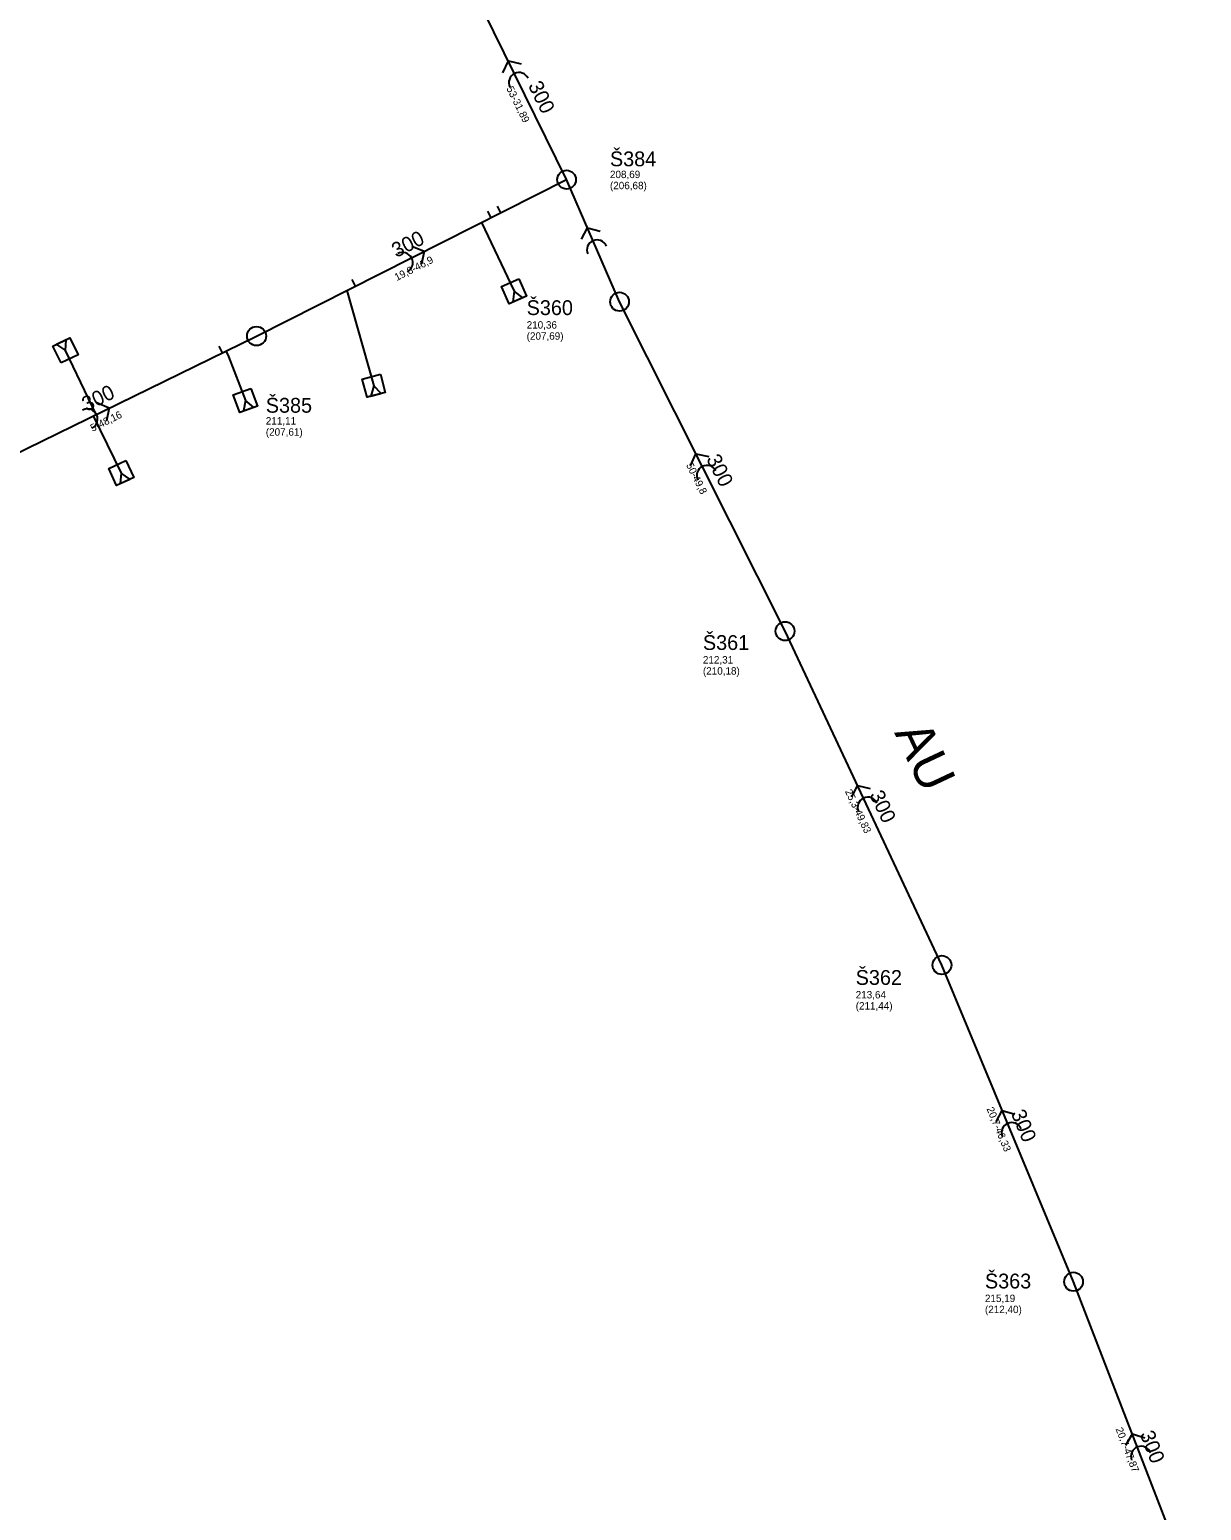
# Model space of a CAD drawing. Extents: x -574467 to -573663, y -1191209 to -1190406.
# Drawn here: x -573886.4 to -573728.1, y -1191008.6 to -1190808.6 of the extents above; entities that cross this region are included whole.
import ezdxf

# ---------------------------------------------------------------- set-up
doc = ezdxf.new("R2010")
doc.units = 0
for name, color, linetype in [('Vrstva 1', 7, 'Continuous'), ('Vrstva 12', 7, 'Continuous'), ('Vrstva 15', 7, 'Continuous'), ('Vrstva 29', 7, 'Continuous'), ('Vrstva 35', 7, 'Continuous'), ('Vrstva 41', 7, 'Continuous'), ('Vrstva 44', 7, 'Continuous'), ('Vrstva 45', 7, 'Continuous'), ('Vrstva 56', 7, 'Continuous'), ('Vrstva 57', 7, 'Continuous')]:
    doc.layers.add(name, color=color, linetype=linetype)

# ---------------------------------------------------------------- blocks, each defined once
blk = doc.blocks.new('100')
at = {"layer": 'Vrstva 1'}
blk.add_circle((0, 0), 1.27, dxfattribs=at)
blk = doc.blocks.new('105')
at = {"layer": 'Vrstva 1'}
blk.add_lwpolyline([(-1.27, 1.27), (1.27, 1.27), (1.27, -1.27), (-1.27, -1.27), (-1.27, 1.27)], dxfattribs=at)
blk = doc.blocks.new('106')
at = {"layer": 'Vrstva 1'}
for p, q in [((1.25, 0.72), (0, 0)), ((0, 0), (1.25, -0.72)), ((1.25, -0.72), (1.25, 0.72))]:
    blk.add_line(p, q, dxfattribs=at)
blk = doc.blocks.new('86')
at = {"layer": 'Vrstva 1'}
blk.add_lwpolyline([(0.79, 1.37), (1.89, 0), (0.79, -1.38)], dxfattribs=at)
blk.add_arc((-1.37, 0), 1.37, 270, 90, dxfattribs=at)

msp = doc.modelspace()

# ---------------------------------------------------------------- linework, layer by layer
at = {"layer": 'Vrstva 12'}
for p, q in [((-573824.041, -1190834.019), (-573824.491, -1190833.126)), ((-573822.719, -1190833.353), (-573823.169, -1190832.46)), ((-573825.335, -1190834.673), (-573820.951, -1190843.961)), ((-573843.515, -1190843.84), (-573839.9, -1190856.726)), ((-573842.372, -1190843.263), (-573842.822, -1190842.371)), ((-573877.396, -1190860.603), (-573881.549, -1190851.948)), ((-573860.339, -1190852.255), (-573860.778, -1190851.357)), ((-573877.801, -1190860.801), (-573874.018, -1190868.508))]:
    msp.add_line(p, q, dxfattribs=at)
msp.add_lwpolyline([(-573859.863, -1190852.022), (-573859.5, -1190852.764), (-573857.242, -1190858.704)], dxfattribs=at)
at = {"layer": 'Vrstva 15'}
for p, q in [((-573855.73, -1190850), (-573813.849, -1190828.881)), ((-573806.69, -1190845.37), (-573813.849, -1190828.881)), ((-573784.34, -1190889.87), (-573806.69, -1190845.37)), ((-573898.99, -1190871.17), (-573855.73, -1190850)), ((-573763.14, -1190934.97), (-573784.34, -1190889.87)), ((-573745.36, -1190977.75), (-573763.14, -1190934.97)), ((-573728.09, -1191022.4), (-573745.36, -1190977.75))]:
    msp.add_line(p, q, dxfattribs=at)
msp.add_lwpolyline([(-573813.849, -1190828.881), (-573813.865, -1190828.843), (-573827.9, -1190800.25)], dxfattribs=at)

# ---------------------------------------------------------------- block references
at = {"layer": 'Vrstva 12'}
for name, p, xscale, yscale, rotation in [('105', (-573820.951, -1190843.961), 0.9999999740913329, 0.9999999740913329, -65.99999939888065), ('106', (-573820.951, -1190843.961), 0.9999999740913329, 0.9999999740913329, -65.99999939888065), ('105', (-573881.549, -1190851.948), 0.9999999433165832, 0.999999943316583, 115.9999999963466), ('106', (-573881.549, -1190851.948), 0.9999999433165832, 0.999999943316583, 115.9999999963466), ('105', (-573839.9, -1190856.726), 0.999999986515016, 0.9999999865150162, -74.99999987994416), ('105', (-573857.242, -1190858.704), 0.9999999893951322, 0.9999999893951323, -70.00000094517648), ('106', (-573839.9, -1190856.726), 0.999999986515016, 0.9999999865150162, -74.99999987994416), ('106', (-573857.242, -1190858.704), 0.9999999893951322, 0.9999999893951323, -70.00000094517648), ('105', (-573874.018, -1190868.508), 0.9999999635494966, 0.9999999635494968, -65.00000039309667), ('106', (-573874.018, -1190868.508), 0.9999999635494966, 0.9999999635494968, -65.00000039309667)]:
    msp.add_blockref(name, p, dxfattribs=dict(at, xscale=xscale, yscale=yscale, rotation=rotation))
at = {"layer": 'Vrstva 29'}
for p, xscale, yscale, rotation in [((-573813.849, -1190828.881), 0.9999999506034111, 0.9999999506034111, -67.99999971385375), ((-573806.69, -1190845.37), 0.9999999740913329, 0.9999999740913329, -65.99999939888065), ((-573855.73, -1190850), 1.0138864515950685, 1.0138864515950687, 27.5653151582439), ((-573784.34, -1190889.87), 0.9999999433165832, 0.999999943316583, 115.9999999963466), ((-573763.14, -1190934.97), 0.9999999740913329, 0.9999999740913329, 114.00000060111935), ((-573745.36, -1190977.75), 0.9999999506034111, 0.9999999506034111, 112.00000028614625)]:
    msp.add_blockref('100', p, dxfattribs=dict(at, xscale=xscale, yscale=yscale, rotation=rotation))
at = {"layer": 'Vrstva 41'}
for p, xscale, yscale, rotation in [((-573820.883, -1190814.547), 0.9999999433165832, 0.999999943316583, 115.9999999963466), ((-573810.269, -1190837.125), 0.9999999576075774, 0.9999999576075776, 113.00000088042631), ((-573834.789, -1190839.44), 1.0106517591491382, 1.010651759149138, 28.162115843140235), ((-573877.36, -1190860.585), 1.0138864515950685, 1.0138864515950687, 27.5653151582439), ((-573795.515, -1190867.62), 0.999999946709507, 0.999999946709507, 117.00000088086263), ((-573773.74, -1190912.42), 0.9999999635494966, 0.9999999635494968, 114.99999960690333), ((-573754.25, -1190956.36), 0.9999999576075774, 0.9999999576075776, 113.00000088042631), ((-573736.725, -1191000.075), 0.999999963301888, 0.9999999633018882, 110.99999898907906)]:
    msp.add_blockref('86', p, dxfattribs=dict(at, xscale=xscale, yscale=yscale, rotation=rotation))

# ---------------------------------------------------------------- texts
at = {"layer": 'Vrstva 35'}
msp.add_text('AU', height=5, rotation=295.18, dxfattribs=at).set_placement((-573769.611, -1190903.574))
at = {"layer": 'Vrstva 44'}
for rotation, p in [(296.14, (-573819.095, -1190816.151)), (26.76, (-573836.852, -1190839.466)), (26.08, (-573878.714, -1190860.245)), (296.67, (-573795.024, -1190866.588)), (295.18, (-573772.972, -1190911.944)), (292.57, (-573753.852, -1190954.975)), (291.15, (-573736.438, -1190998.314))]:
    msp.add_text('300', height=2, rotation=rotation, dxfattribs=at).set_placement(p)
at = {"layer": 'Vrstva 45'}
for s, rotation, p in [('53-31,89', 296.14, (-573822.008, -1190816.558)), ('19,8-46,9', 26.76, (-573836.787, -1190842.583)), ('5-48,16', 26.08, (-573877.885, -1190862.96)), ('50-49,8', 296.67, (-573797.736, -1190867.434)), ('25,3-49,83', 295.18, (-573776.266, -1190911.506)), ('20,7-46,33', 292.57, (-573757.131, -1190954.387)), ('20,7-47,87', 291.15, (-573739.699, -1190997.643))]:
    msp.add_text(s, height=1, rotation=rotation, dxfattribs=at).set_placement(p)
at = {"layer": 'Vrstva 56'}
for s, p in [('208,69 ', (-573807.989, -1190828.671)), ('(206,68)', (-573807.989, -1190830.171)), ('210,36 ', (-573819.24, -1190849)), ('(207,69)', (-573819.24, -1190850.5)), ('211,11 ', (-573854.48, -1190861.96)), ('(207,61)', (-573854.48, -1190863.46)), ('212,31 ', (-573795.43, -1190894.24)), ('(210,18)', (-573795.43, -1190895.74)), ('213,64 ', (-573774.79, -1190939.48)), ('(211,44)', (-573774.79, -1190940.98)), ('215,19 ', (-573757.33, -1190980.49)), ('(212,40)', (-573757.33, -1190981.99))]:
    msp.add_text(s, height=1, dxfattribs=at).set_placement(p)
at = {"layer": 'Vrstva 57'}
for s, p in [('Š384', (-573807.989, -1190827.071)), ('Š360', (-573819.24, -1190847.17)), ('Š385', (-573854.48, -1190860.36)), ('Š361', (-573795.43, -1190892.41)), ('Š362', (-573774.79, -1190937.65)), ('Š363', (-573757.33, -1190978.66))]:
    msp.add_text(s, height=2, dxfattribs=at).set_placement(p)

doc.saveas('drawing.dxf')
